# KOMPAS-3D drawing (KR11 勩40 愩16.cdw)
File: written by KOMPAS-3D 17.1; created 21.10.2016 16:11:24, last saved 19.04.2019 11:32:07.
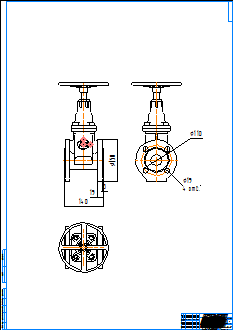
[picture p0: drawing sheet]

Sheet 1: A0, portrait

Title block, sheet 1: name: KR11 Ду40 Ру16; material: Внимание! Данный продукт является объектом авторского права ООО «Торговый Дом АДЛ». / Запрещается изменение, копирование, распространение / (в том числе путем копирования на другие сайты и ресурсы в Интернете) / или любое иное использование информации и объектов без предварительного / согласия правообладателя (ООО «Торговый Дом АДЛ»).; mass: 14,1; sheets: 1; organisation: ООО "Торговый дом АДЛ"; sheet format: A0; stored path: \\adlc.lan\data\АДЛ_ПКД\3D-модели\ADL production\Клиновые задвижки серии KR ГРАНАР\Клиновые задвижки KR11\KOMPAS 2D\KR11 Ду40 Ру16.cdw

Views: Спереди 4, Проекционный вид 5, Проекционный вид 6
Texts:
  Klimkovich
  ADL
Dimensions and other numbers on the sheet: 19; 110; 4 отв.; 140; 3; 150; 1:1; 1; 14,1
